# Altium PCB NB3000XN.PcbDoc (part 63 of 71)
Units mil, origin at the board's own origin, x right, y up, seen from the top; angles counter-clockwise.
Board outline 9527.56 x 6929.77 mil, 6 copper layers (Top Layer, GND+SHIELD, MidLayer1, MidLayer2, P2 - 3V3+5V0, Bottom Layer), stack 62.375 mil thick; 832 components, 1027 nets, 4655 pads, 4981 vias.
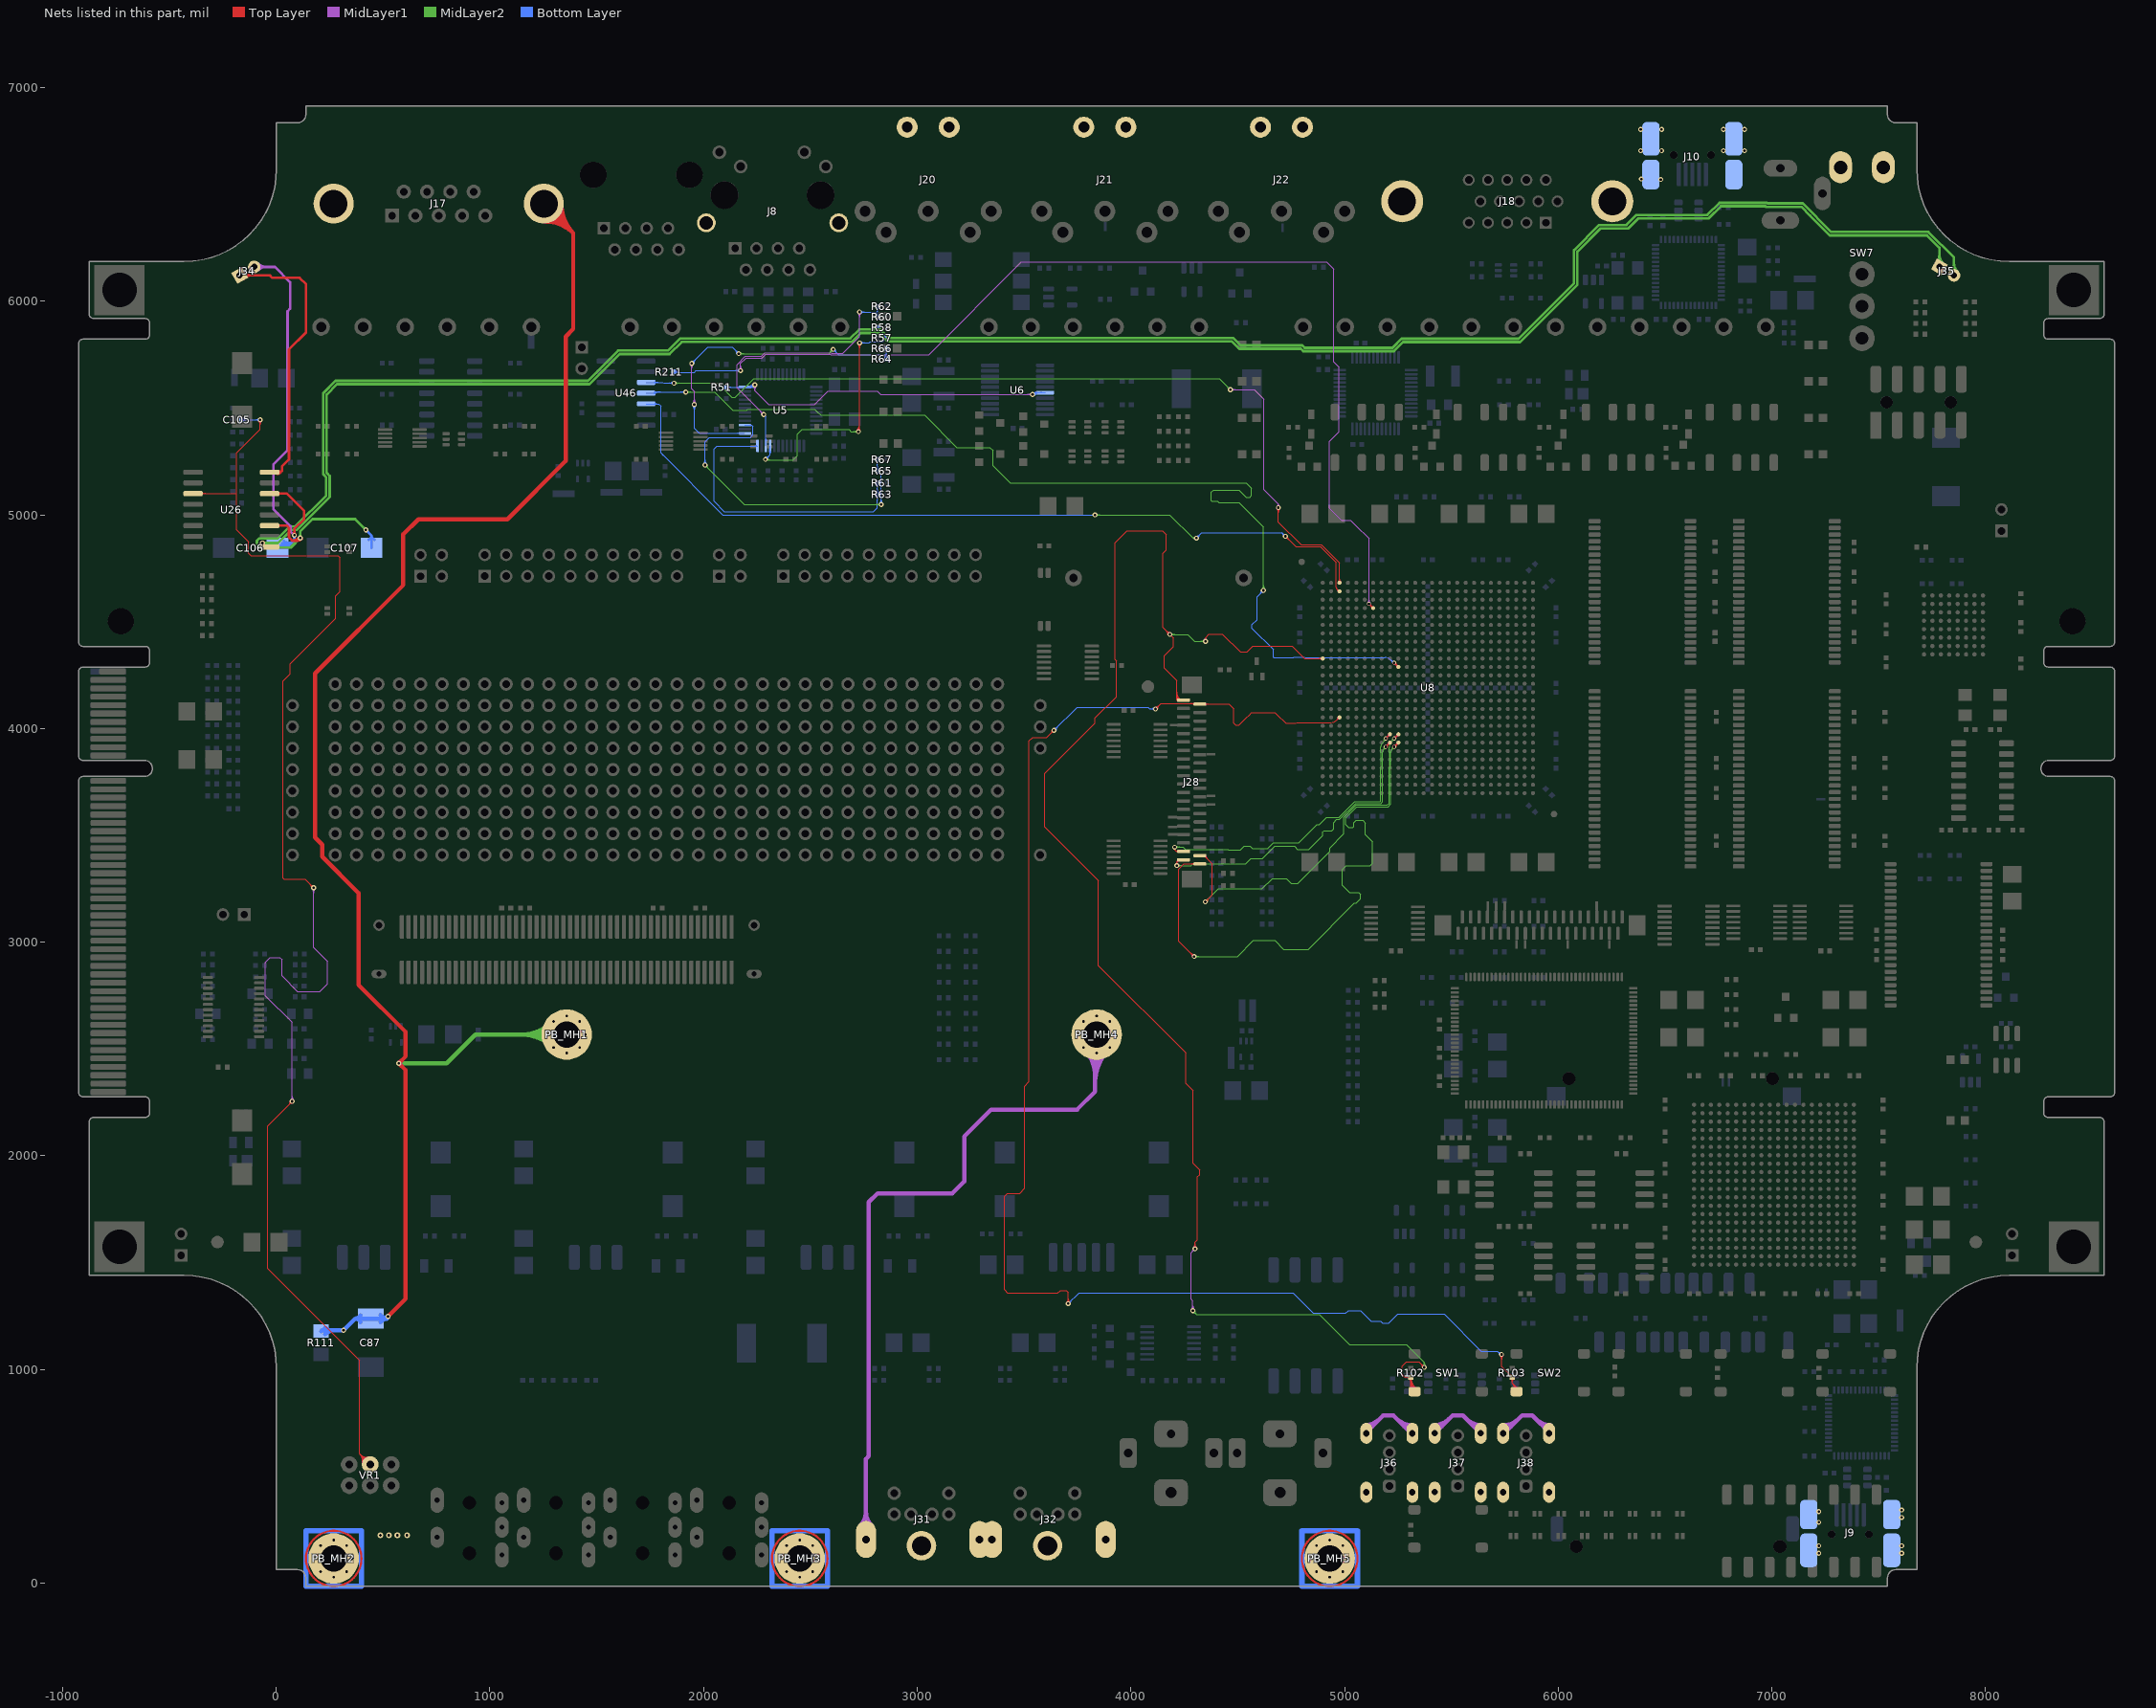
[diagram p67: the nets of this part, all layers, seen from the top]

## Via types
v1: diameter 23, hole 11.81, Top Layer to Bottom Layer, 3672 vias
v2: diameter 26, hole 11.81, Top Layer to Bottom Layer, 461 vias
v3: diameter 19, hole 11.81, Top Layer to Bottom Layer, tented both sides, 396 vias
v4: diameter 23.62, hole 11.81, Top Layer to Bottom Layer, 288 vias
v5: diameter 20, hole 11.81, Top Layer to Bottom Layer, 91 vias
v6: diameter 23, hole 11.81, Top Layer to Bottom Layer, tented both sides, 50 vias
v7: diameter 31, hole 11.81, Top Layer to Bottom Layer, 15 vias
v8: diameter 27.56, hole 11.81, Top Layer to Bottom Layer, tented both sides, 4 vias
v9: diameter 29, hole 11.81, Top Layer to Bottom Layer, 3 vias
v10: diameter 21, hole 11.81, Top Layer to Bottom Layer, 1 vias

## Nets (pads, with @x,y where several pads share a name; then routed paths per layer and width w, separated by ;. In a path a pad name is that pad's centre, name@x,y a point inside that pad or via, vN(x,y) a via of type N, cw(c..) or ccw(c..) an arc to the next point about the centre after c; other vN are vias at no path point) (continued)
RS485.RX_EN: U8.A3 U46.3 | length 4535.4
  Top Layer w4: v1@4683.47,5027.66 cw(c4667.26,5011.44) 4690.19,5011.44 cw(c4713.13,5011.44) v1@4696.91,5027.66 ; v1@4686.3,5030.49 cw(c4676.91,5021.1) 4690.19,5021.1 cw(c4703.47,5021.1) v1@4694.08,5030.49 ; v1(4690.19,5034.37) 4690.19,4966.71 4797.19,4859.71 4891.61,4859.71 4976.61,4774.7 4976.61,4724.74 4976.61,4720 4976.61,4710 U8.A3@4976.61,4682.13 ; U8.A3@4971.31,4687.43 ccw(c4958.51,4700.23) 4976.61,4700.23 ccw(c4994.72,4700.23) U8.A3@4981.92,4687.43 ; U8.A3@4971.42,4687.32 ccw(c4958.89,4699.85) 4976.61,4699.85 ccw(c4994.34,4699.85) U8.A3@4981.81,4687.32
  MidLayer1 w4: v1(4466.19,5586.04) 4578.96,5586.04 4623.52,5541.48 4623.52,5117.71 4690.19,5051.04 ; v1@4470.08,5582.15 cw(c4479.47,5572.76) 4479.47,5586.04 cw(c4479.47,5599.32) v1@4470.08,5589.93 ; v1@4472.91,5579.32 cw(c4489.13,5563.11) 4489.13,5586.04 cw(c4489.13,5608.98) v1@4472.91,5592.76 ; v1@4685.35,5042.55 ccw(c4680.32,5051.04) 4690.19,5051.04 ; v1(4690.19,5034.37) 4690.19,5051.04 ; v1@4695.03,5042.55 cw(c4700.06,5051.04) 4690.19,5051.04
  MidLayer2 w4: v1(1861.86,5616.71) 2065.19,5616.71 2131.86,5550.04 2148.52,5550.04 2231.86,5633.37 2236.29,5637.81 4414.42,5637.81 4418.86,5633.37 v1(4466.19,5586.04) ; v1@4456.69,5586.04 ccw(c4433.76,5586.04) 4449.97,5602.26 ccw(c4466.19,5618.48) v1@4466.19,5595.54 ; v1@4460.69,5586.04 ccw(c4447.41,5586.04) 4456.8,5595.43 ccw(c4466.19,5604.82) v1@4466.19,5591.54 ; 1875.14,5616.71 cw(c1875.14,5629.99) 1865.75,5620.6 ccw(c1875.14,5629.99) 1875.14,5616.71 ; 1875.14,5616.71 ccw(c1875.14,5603.43) 1865.75,5612.82 cw(c1875.14,5603.43) 1875.14,5616.71 ; 1884.79,5616.71 cw(c1884.79,5639.64) 1868.57,5623.43 ccw(c1884.79,5639.64) 1884.79,5616.71 ; 1884.79,5616.71 ccw(c1884.79,5593.77) 1868.57,5609.99 cw(c1884.79,5593.77) 1884.79,5616.71
  Bottom Layer w4: U46.3@1731.54,5620.08 1810,5620.08 1813.37,5616.71 v1(1861.86,5616.71) ; U46.3@1767.15,5615.97 cw(c1777.07,5606.05) 1777.07,5620.08 cw(c1777.07,5634.11) U46.3@1767.15,5624.19 ; U46.3@1769.98,5613.14 cw(c1786.72,5596.39) 1786.72,5620.08 cw(c1786.73,5643.76) U46.3@1769.98,5627.01 ; v1@1855.14,5609.99 ccw(c1838.92,5593.77) 1838.92,5616.71 ccw(c1838.92,5639.64) v1@1855.14,5623.43 ; v1@1857.97,5612.82 ccw(c1848.58,5603.43) 1848.58,5616.71 ccw(c1848.58,5629.99) v1@1857.97,5620.6
RS485.RXD: R211.1 U8.D7 | length 5431
  Top Layer w4: v3(5114.41,4583.7) U8.D7@5134.09,4564.02 ; U8.D7@5126.59,4564.02 ccw(c5108.49,4564.02) 5121.29,4576.82 ccw(c5134.09,4589.62) U8.D7@5134.09,4571.52 ; U8.D7@5126.75,4564.02 ccw(c5109.03,4564.02) 5121.56,4576.55 ccw(c5134.09,4589.08) U8.D7@5134.09,4571.36 ; 5127.21,4570.9 ccw(c5114.41,4558.09) 5114.41,4576.2 cw(c5114.41,4558.09) 5127.21,4570.9 ; 5127.21,4570.9 cw(c5140.02,4583.7) 5121.91,4583.7 ccw(c5140.02,4583.7) 5127.21,4570.9
  MidLayer1 w4: v1@2166.81,5681.76 ccw(c2150.59,5697.98) 2173.52,5697.98 ccw(c2196.46,5697.98) v1@2180.24,5681.76 ; v1@2169.64,5678.93 ccw(c2160.25,5688.32) 2173.52,5688.32 ccw(c2186.8,5688.32) v1@2177.41,5678.93 ; v1(2173.52,5675.04) 2173.52,5708.52 2199.21,5734.21 2274.21,5734.21 2291,5751 2594.84,5751 2596.29,5749.54 3054.54,5749.54 3488.37,6183.37 4916.63,6183.37 4950,6150 4950,5715.23 4973.52,5691.71 4973.52,5389.04 4929.52,5345.04 4929.52,5030.94 4985.43,4975.04 5028.45,4975.04 5051.23,4952.26 ; 5050,4953.49 5114.41,4889.08 5114.41,4720 5114.41,4710 5114.41,4661.38 v3(5114.41,4583.7) ; v3@5109.22,4588.89 ccw(c5096.68,4601.43) 5114.41,4601.43 ccw(c5132.14,4601.43) v3@5119.6,4588.89 ; 5114.41,4601.81 ccw(c5132.52,4601.81) 5119.71,4589 cw(c5132.52,4601.81) 5114.41,4601.81 ; 5114.41,4601.81 cw(c5096.3,4601.81) 5109.11,4589 ccw(c5096.3,4601.81) 5114.41,4601.81
  Bottom Layer w4: R211.1@1861.18,5670 1861.18,5666.71 1956.86,5666.71 1965.19,5675.04 v1(2173.52,5675.04) ; R211.1@1864.94,5673.27 ccw(c1880.78,5689.11) 1880.78,5666.71 ; R211.1@1867.77,5662.92 cw(c1876.92,5653.77) 1876.92,5666.71 ; R211.1@1867.77,5676.1 ccw(c1890.44,5698.77) 1890.44,5666.71 ; v1@2166.81,5668.32 ccw(c2150.59,5652.11) 2150.59,5675.04 ccw(c2150.59,5697.98) v1@2166.81,5681.76 ; v1@2169.64,5671.15 ccw(c2160.25,5661.76) 2160.25,5675.04 ccw(c2160.25,5688.32) v1@2169.64,5678.93
RS485.TX_EN: U8.L10 U46.4 | length 5352.4
  Top Layer w4: v3(5232.52,4308.11) U8.L10@5252.2,4288.43 ; U8.L10@5244.7,4288.43 ccw(c5226.6,4288.43) 5239.4,4301.23 ccw(c5252.2,4314.03) U8.L10@5252.2,4295.93 ; U8.L10@5244.86,4288.43 ccw(c5227.14,4288.43) 5239.67,4300.96 ccw(c5252.2,4313.49) U8.L10@5252.2,4295.77 ; 5245.32,4295.31 cw(c5258.13,4308.11) 5240.02,4308.11 ccw(c5258.13,4308.11) 5245.32,4295.31 ; 5245.32,4295.31 ccw(c5232.52,4282.5) 5232.52,4300.61 cw(c5232.52,4282.5) 5245.32,4295.31
  MidLayer2 w4: v1(1916.86,5575.04) 2051.86,5575.04 2127.99,5498.91 2137.02,5489.88 2201.5,5489.88 2207.17,5495.54 2519.69,5495.54 2533.5,5481.74 2548.52,5466.71 3034.84,5466.71 3185.41,5316.14 3340.18,5316.14 3355,5301.31 3355,5230 3434.96,5150.04 4540.19,5150.04 4565.19,5125.04 4565.19,5091.71 4556.86,5083.37 4540.19,5083.37 4506.86,5116.71 4386.71,5116.71 4377.28,5107.28 4377.28,5067.72 4379.5,5065.5 4405.56,5065.5 4412.69,5058.37 4506.86,5058.37 4590.12,4975.12 ; v1@1920.75,5571.15 cw(c1930.14,5561.76) 1930.14,5575.04 cw(c1930.14,5588.32) v1@1920.75,5578.93 ; v1@1923.57,5568.32 cw(c1939.79,5552.11) 1939.79,5575.04 cw(c1939.79,5597.98) v1@1923.57,5581.76 ; 4590,4975 4620.52,4944.48 v1(4620.52,4647.04) ; v1@4613.81,4653.76 ccw(c4597.59,4669.98) 4620.52,4669.98 ccw(c4643.46,4669.98) v1@4627.24,4653.76 ; v1@4616.64,4650.93 ccw(c4607.25,4660.32) 4620.52,4660.32 ccw(c4633.8,4660.32) v1@4624.41,4650.93
  Bottom Layer w4: U46.4@1731.54,5570.08 1763.04,5570.08 1765.19,5570.08 1765.19,5570.37 1769.86,5575.04 v1(1916.86,5575.04) ; U46.4@1764.32,5568.8 cw(c1779.39,5553.72) 1779.39,5575.04 ; U46.4@1767.15,5565.97 cw(c1789.05,5544.07) 1789.05,5575.04 ; U46.4@1769.98,5563.14 cw(c1798.71,5534.41) 1798.71,5575.04 ; U46.4@1769.98,5577.01 ccw(c1774.74,5581.78) U46.4@1774.74,5575.04 ; v1@1910.14,5568.32 ccw(c1893.92,5552.11) 1893.92,5575.04 ccw(c1893.92,5597.98) v1@1910.14,5581.76 ; v1@1912.97,5571.15 ccw(c1903.58,5561.76) 1903.58,5575.04 ccw(c1903.58,5588.32) v1@1912.97,5578.93 ; v1@4611.02,4647.04 cw(c4588.09,4647.04) 4604.31,4630.82 cw(c4620.52,4614.61) v1@4620.52,4637.54 ; v1@4615.02,4647.04 cw(c4601.75,4647.04) 4611.13,4637.65 cw(c4620.52,4628.26) v1@4620.52,4641.54 ; v1(4620.52,4647.04) 4590.19,4616.71 4590.19,4508.63 4567.5,4485.94 4567.5,4469.69 4667.19,4370 4667.19,4333.37 4668.52,4332.04 4761.88,4332.04 4764.84,4335 4813.75,4335 4816.78,4331.97 4860,4331.97 4870,4331.97 5076.1,4331.97 5095.52,4331.97 5169.64,4331.97 5189.14,4331.97 cw(c5189.14,4290.24) 5218.65,4319.75 ; v3@5225.05,4307.46 ccw(c5207.01,4305.88) 5218.65,4319.75 ; v3@5231.87,4315.58 cw(c5230.29,4333.62) 5218.65,4319.75
RS485.TXD: U8.B3 U46.5 | length 4162.6
  Top Layer w4: v1@4723.52,4890.54 cw(c4723.52,4867.61) 4739.74,4883.82 cw(c4755.96,4900.04) v1@4733.02,4900.04 ; v1@4723.52,4894.54 cw(c4723.52,4881.26) 4732.91,4890.65 cw(c4742.3,4900.04) v1@4729.02,4900.04 ; v1(4723.52,4900.04) 4771.86,4851.71 4888.17,4851.71 4889.67,4850.21 4889.79,4850.21 4961.11,4778.89 4961.11,4720 ; 4961.11,4724.74 4961.11,4720 ; 4961.11,4662.47 ccw(c4971.26,4662.47) 4964.08,4655.29 ; 4961.11,4662.47 ccw(c4971.26,4662.47) 4964.08,4655.29 ; 4961.11,4662.47 4961.11,4710 4961.11,4720 ; 4964.08,4655.29 ccw(c4976.61,4667.83) 4976.61,4650.1 cw(c4976.61,4667.83) 4964.08,4655.29 ; 4964.08,4655.29 cw(c4951.55,4642.76) 4969.27,4642.76 ccw(c4951.55,4642.76) 4964.08,4655.29
  MidLayer2 w4: v1(3831.86,5000.04) 4181.86,5000.04 4290.19,4891.71 ; v1@3835.75,4996.15 cw(c3845.14,4986.76) 3845.14,5000.04 cw(c3845.14,5013.32) v1@3835.75,5003.93 ; v1@3838.57,4993.32 cw(c3854.79,4977.11) 3854.79,5000.04 cw(c3854.79,5022.98) v1@3838.57,5006.76 ; v1@4298.68,4886.87 ccw(c4290.19,4881.84) 4290.19,4891.71 ; v1@4298.68,4896.55 cw(c4290.19,4901.58) 4290.19,4891.71 ; v1(4306.86,4891.71) 4290.19,4891.71
  Bottom Layer w4: U46.5@1731.54,5520.08 1780,5520.08 ; U46.5@1771.54,5515.19 cw(c1780,5510.32) 1780,5520.08 ; U46.5@1771.54,5524.97 ccw(c1780,5529.83) 1780,5520.08 ; 1810.61,5279.62 1800,5290.23 ; v1(3831.86,5000.04) 2090.19,5000.04 1800,5290.23 ; v1(4306.86,4891.71) 4332.19,4917.04 4706.52,4917.04 v1(4723.52,4900.04) ; v1@4306.86,4897.21 ccw(c4306.86,4910.49) 4316.25,4901.1 ccw(c4325.64,4891.71) v1@4312.36,4891.71 ; v1@4306.86,4901.21 ccw(c4306.86,4924.14) 4323.07,4907.93 ccw(c4339.29,4891.71) v1@4316.36,4891.71 ; v1@4714.02,4900.04 ccw(c4691.09,4900.04) 4707.31,4916.26 ccw(c4723.52,4932.48) v1@4723.52,4909.54 ; v1@4718.02,4900.04 ccw(c4704.75,4900.04) 4714.14,4909.43 ccw(c4723.52,4918.82) v1@4723.52,4905.54 ; 1780,5520.08 1789.92,5520.08 1800,5510 1800,5290.23
RXER_U: R51.1 U5.24 U6.6 | length 2078.5
  MidLayer1 w4: v1@2233.47,5601.66 cw(c2217.26,5585.44) 2240.19,5585.44 cw(c2263.13,5585.44) v1@2246.91,5601.66 ; v1@2236.3,5604.49 cw(c2226.91,5595.1) 2240.19,5595.1 cw(c2253.47,5595.1) v1@2244.08,5604.49 ; v1(2240.19,5608.37) 2240.19,5581.37 2304.86,5516.71 2456.86,5516.71 2520.39,5516.71 2582.69,5579 2813.82,5579 2828.78,5564.04 v1(3540.19,5564.04) ; v1@3533.47,5557.32 ccw(c3517.26,5541.11) 3517.26,5564.04 ccw(c3517.26,5586.98) v1@3533.47,5570.76 ; v1@3536.3,5560.15 ccw(c3526.91,5550.76) 3526.91,5564.04 ccw(c3526.91,5577.32) v1@3536.3,5567.93
  Bottom Layer w4: R51.1@2106.18,5598.33 U5.24@2193.48,5598.33 ; R51.1@2109.94,5594.57 cw(c2119.02,5585.49) 2119.02,5598.33 cw(c2119.02,5611.18) R51.1@2109.94,5602.09 ; R51.1@2112.77,5591.74 cw(c2128.68,5575.84) 2128.68,5598.33 cw(c2128.68,5620.83) R51.1@2112.77,5604.92 ; 2160.2,5598.33 cw(c2160.2,5588.45) U5.24@2167.19,5595.44 ; 2160.52,5598.33 ccw(c2160.52,5607.77) U5.24@2167.19,5601.1 ; U5.24@2203.06,5598.27 ccw(c2203.06,5644.73) v1@2236.26,5612.22 ; U5.24@2212.58,5598.27 ccw(c2212.58,5635.42) v1@2239.12,5609.42 ; U5.24@2219.9,5595.44 cw(c2226.73,5588.61) 2226.73,5598.27 cw(c2226.73,5607.92) U5.24@2219.9,5601.1 ; U5.24@2222.09,5598.27 ccw(c2222.09,5626.1) v1@2241.98,5606.63 ; 2231.61,5598.27 ccw(c2231.61,5616.78) v1@2244.83,5603.83 ; v1@2233.4,5615.02 cw(c2193.55,5654.05) U5.24@2193.54,5598.27 2238.42,5598.27 2240.19,5600.04 v1(2240.19,5608.37) ; v1@3538.42,5565.81 cw(c3553.86,5550.37) 3553.86,5572.2 ; v1(3540.19,5564.04) 3548.35,5572.2 U6.6@3598.94,5572.2 ; v1@3541.25,5562.98 cw(c3563.52,5540.71) U6.6@3563.52,5572.2 ; v1@3544.08,5560.15 cw(c3573.18,5531.05) U6.6@3573.18,5572.2 ; v1@3546.91,5557.32 cw(c3582.83,5521.4) U6.6@3582.83,5572.2 ; U6.6@3560.62,5567.36 ccw(c3548.92,5555.65) 3548.92,5572.2 ccw(c3548.92,5588.76) U6.6@3560.62,5577.05
S_LED0: R57.1 R58.1 U5.9 | length 1810.4
  Top Layer w4: v4@2718.06,5396.94 ccw(c2689.24,5425.76) 2730,5425.76 ; v4@2720.89,5394.11 ccw(c2698.9,5416.1) 2730,5416.1 ; v4@2723.06,5798.06 cw(c2706.31,5781.31) 2730,5781.31 cw(c2753.69,5781.31) v4@2736.94,5798.06 ; v4@2723.72,5391.28 ccw(c2708.56,5406.44) 2730,5406.44 ; v4(2725,5390) 2730,5395 v4(2730,5805) ; v4@2725.89,5800.89 cw(c2715.97,5790.97) 2730,5790.97 cw(c2744.03,5790.97) v4@2734.11,5800.89 ; 2730,5401.61 ccw(c2736.61,5401.61) v4@2731.94,5396.94
  MidLayer2 w4: v4(2290,5260) 2292.46,5257.54 2420,5257.54 2439.7,5277.24 2439.7,5377.53 2462.7,5400.54 2680,5400.54 2690.54,5390 v4(2725,5390) ; v4@2294.11,5264.11 ccw(c2309.97,5279.97) 2309.97,5257.54 ; v4@2296.94,5253.06 cw(c2307.75,5242.25) 2307.75,5257.54 ; v4@2296.94,5266.94 ccw(c2319.62,5289.62) 2319.62,5257.54 ; v4@2718.06,5383.06 ccw(c2701.31,5366.31) 2701.31,5390 ccw(c2701.31,5413.69) v4@2718.06,5396.94 ; v4@2720.89,5385.89 ccw(c2710.97,5375.97) 2710.97,5390 ccw(c2710.97,5404.03) v4@2720.89,5394.11
  Bottom Layer w4: v4(2290,5260) 2311.65,5281.65 U5.9@2311.65,5322.68 ; v4@2290,5265.81 ccw(c2290,5279.84) 2299.92,5269.92 ccw(c2309.84,5260) v4@2295.81,5260 ; v4@2290,5269.81 ccw(c2290,5293.5) 2306.75,5276.75 ccw(c2323.5,5260) v4@2299.81,5260 ; U5.9@2308.82,5296.32 cw(c2302,5289.49) 2311.65,5289.49 cw(c2321.31,5289.49) U5.9@2314.48,5296.32 ; v4(2730,5805) 2774.96,5805 2780,5810.04 2838.22,5810.04 R57.1@2856.18,5828 ; v4@2734.11,5800.89 cw(c2744.03,5790.97) 2744.03,5805 cw(c2744.03,5819.03) v4@2734.11,5809.11 ; v4@2736.94,5798.06 cw(c2753.69,5781.31) 2753.69,5805 cw(c2753.69,5828.69) v4@2736.94,5811.94 ; R58.1@2813.82,5867.19 cw(c2813.82,5843.5) 2830.57,5860.25 ; R58.1@2813.82,5871.19 cw(c2813.82,5857.16) R58.1@2823.74,5867.08 ; R58.1@2813.82,5877 R57.1@2856.18,5834.64 ; R58.1@2819.14,5876.51 ccw(c2830.79,5876.51) R58.1@2822.55,5868.27 ; R58.1@2823.14,5876.51 ccw(c2844.45,5876.51) 2829.38,5861.44 ; 2835.93,5854.89 cw(c2809.53,5828.49) R57.1@2846.86,5828.49 ; 2839.43,5811.25 cw(c2856.18,5794.5) R57.1@2856.18,5818.19 ; 2840.62,5812.44 ccw(c2825.55,5827.51) R57.1@2846.86,5827.51 ; 2842.76,5848.06 cw(c2823.18,5828.49) R57.1@2850.86,5828.49 ; R57.1@2846.26,5818.08 cw(c2856.18,5808.16) R57.1@2856.18,5822.19 ; R57.1@2847.45,5819.27 ccw(c2839.21,5827.51) R57.1@2850.86,5827.51 ; 2849.58,5841.23 cw(c2836.84,5828.49) R57.1@2854.86,5828.49 ; 2850.76,5840.05 ccw(c2856.18,5845.47) R57.1@2856.18,5837.81
S_LED1: R60.2 R62.1 U5.10 | length 1575.8
  MidLayer1 w4: v1@2272.36,5470.04 ccw(c2249.42,5470.04) 2265.64,5486.26 ccw(c2281.86,5502.48) v1@2281.86,5479.54 ; v1@2276.36,5470.04 ccw(c2263.08,5470.04) 2272.47,5479.43 ccw(c2281.86,5488.82) v1@2281.86,5475.54 ; v1(2281.86,5470.04) 2156.02,5595.87 2156.02,5702.34 2195.89,5742.21 2267.21,5742.21 2270.89,5742.21 2287.69,5759 2598.15,5759 2599.61,5757.54 2652.54,5757.54 2730,5835 v1(2730,5950) ; v1@2723.28,5943.28 cw(c2707.06,5927.06) 2730,5927.06 cw(c2752.93,5927.06) v1@2736.72,5943.28 ; v1@2726.11,5946.11 cw(c2716.72,5936.72) 2730,5936.72 cw(c2743.28,5936.72) v1@2733.89,5946.11
  Bottom Layer w4: v1(2281.86,5470.04) 2291.97,5459.93 U5.10@2291.97,5322.68 ; U5.10@2289.14,5349.03 ccw(c2282.31,5355.86) 2291.97,5355.86 ccw(c2301.63,5355.86) U5.10@2294.8,5349.03 ; v1(2730,5950) 2805.49,5950.04 ; v1@2733.89,5946.11 cw(c2743.29,5936.73) 2743.28,5950.01 cw(c2743.27,5963.29) v1@2733.89,5953.89 ; v1@2736.72,5943.29 cw(c2752.95,5927.08) 2752.94,5950.01 cw(c2752.92,5972.95) v1@2736.71,5956.72 ; R62.1@2807.23,5967.92 cw(c2791.32,5952.01) 2813.82,5952.01 cw(c2836.32,5952.01) R62.1@2820.41,5967.92 ; R60.2@2809.58,5934.79 ccw(c2806.06,5941.71) 2813.82,5941.71 ; R62.1@2810.06,5970.75 cw(c2800.98,5961.67) 2813.82,5961.67 cw(c2826.66,5961.67) R62.1@2817.58,5970.75 ; 2813.78,5950.04 2805.49,5950.04 ; R60.2@2813.82,5926 2813.82,5941.71 ; 2813.82,5950 R62.1@2813.82,5975 ; R60.2@2818.05,5934.79 cw(c2821.58,5941.71) 2813.82,5941.71 ; 2805.49,5950.04 2813.82,5941.71
S_LED2: R61.1 R63.1 U5.12 | length 1544.7
  Bottom Layer w4: 2242.62,5322.81 cw(c2242.62,5312.7) U5.12@2249.77,5319.85 ; 2243.26,5322.81 ccw(c2243.26,5332.01) U5.12@2249.77,5325.51 ; U5.12@2252.6,5322.68 2252.46,5322.81 2062.96,5322.81 2048.52,5308.37 2048.52,5064.34 2096.82,5016.04 2796.04,5016.04 2813.82,5033.82 R61.1@2813.82,5150 ; R63.1@2807.23,5087.92 cw(c2791.32,5072.01) 2813.82,5072.01 cw(c2836.32,5072.01) R63.1@2820.41,5087.92 ; R63.1@2807.23,5102.08 ccw(c2791.32,5117.99) 2813.82,5117.99 ccw(c2836.32,5117.99) R63.1@2820.41,5102.08 ; R61.1@2807.23,5142.92 cw(c2791.32,5127.01) 2813.82,5127.01 cw(c2836.32,5127.01) R61.1@2820.41,5142.92 ; R63.1@2810.06,5090.75 cw(c2800.98,5081.67) 2813.82,5081.67 cw(c2826.66,5081.67) R63.1@2817.58,5090.75 ; R63.1@2810.06,5099.25 ccw(c2800.98,5108.33) 2813.82,5108.33 ccw(c2826.66,5108.33) R63.1@2817.58,5099.25 ; R61.1@2810.06,5145.75 cw(c2800.98,5136.67) 2813.82,5136.67 cw(c2826.66,5136.67) R61.1@2817.58,5145.75
S_LED3: R64.2 R66.1 U5.13 | length 2165.1
  MidLayer1 w4: v4@1938.06,5703.06 cw(c1921.31,5686.31) 1945,5686.31 cw(c1968.69,5686.31) v4@1951.94,5703.06 ; v4@1940.89,5705.89 cw(c1930.97,5695.97) 1945,5695.97 cw(c1959.03,5695.97) v4@1949.11,5705.89 ; v4(1945,5710) 1945,5590 1956.86,5578.14 v1(1956.86,5516.71) ; v1@1950.14,5523.43 ccw(c1933.92,5539.64) 1956.86,5539.64 ccw(c1979.79,5539.64) v1@1963.57,5523.43 ; v1@1952.97,5520.6 ccw(c1943.58,5529.99) 1956.86,5529.99 ccw(c1970.14,5529.99) v1@1960.75,5520.6
  MidLayer2 w4: v4(2165,5755) 2586.82,5755 v1(2606.86,5775.04) ; v4@2169.11,5750.89 cw(c2179.03,5740.97) 2179.03,5755 cw(c2179.03,5769.03) v4@2169.11,5759.11 ; v4@2171.94,5748.06 cw(c2188.69,5731.31) 2188.69,5755 cw(c2188.69,5778.69) v4@2171.94,5761.94 ; v1@2597.36,5775.04 cw(c2574.42,5775.04) 2590.64,5758.82 cw(c2606.86,5742.61) v1@2606.86,5765.54 ; v1@2601.36,5775.04 cw(c2588.08,5775.04) 2597.47,5765.65 cw(c2606.86,5756.26) v1@2606.86,5769.54
  Bottom Layer w4: v4(1945,5710) 2020,5785 2135,5785 v4(2165,5755) ; v4@1945,5715.81 ccw(c1945,5729.84) 1954.92,5719.92 ccw(c1964.84,5710) v4@1950.81,5710 ; v4@1945,5719.81 ccw(c1945,5743.5) 1961.75,5726.75 ccw(c1978.5,5710) v4@1954.81,5710 ; v1@1950.14,5509.99 cw(c1933.92,5493.77) 1956.86,5493.77 cw(c1979.79,5493.77) v1@1963.57,5509.99 ; v1@1952.97,5512.82 cw(c1943.58,5503.43) 1956.86,5503.43 cw(c1970.14,5503.43) v1@1960.75,5512.82 ; v1(1956.86,5516.71) 1956.86,5405 1980.13,5381.73 U5.13@2193.54,5381.73 ; v4@2155.19,5755 ccw(c2131.5,5755) 2148.25,5771.75 ccw(c2165,5788.5) v4@2165,5764.81 ; v4@2159.19,5755 ccw(c2145.16,5755) 2155.08,5764.92 ccw(c2165,5774.84) v4@2165,5760.81 ; U5.13@2167.19,5378.9 ccw(c2160.36,5372.08) 2160.36,5381.73 ccw(c2160.36,5391.39) U5.13@2167.19,5384.56 ; v1@2606.86,5765.54 cw(c2606.86,5742.61) 2623.07,5758.82 cw(c2639.29,5775.04) v1@2616.36,5775.04 ; v1@2606.86,5769.54 cw(c2606.86,5756.26) 2616.25,5765.65 cw(c2625.64,5775.04) v1@2612.36,5775.04 ; v1(2606.86,5775.04) 2631.86,5750.04 2854.51,5750.04 2856.18,5751.71 ; R66.1@2849.59,5771.92 cw(c2833.68,5756.01) 2856.18,5756.01 cw(c2878.68,5756.01) R66.1@2862.77,5771.92 ; R64.2@2849.88,5737.35 ccw(c2836.69,5751.71) 2856.18,5751.71 ; R66.1@2852.42,5774.75 cw(c2843.34,5765.67) 2856.18,5765.67 cw(c2869.02,5765.67) R66.1@2859.94,5774.75 ; R64.2@2852.58,5734.41 ccw(c2845.06,5742.6) 2856.18,5742.6 ccw(c2867.3,5742.6) R64.2@2859.78,5734.41 ; R64.2@2856.18,5730 2856.18,5751.71 ; R66.1@2856.18,5779 2856.18,5751.71 ; R64.2@2862.49,5737.35 cw(c2875.67,5751.71) 2856.18,5751.71
S_LED4: R65.1 R67.1 U5.15 | length 1954.1
  MidLayer2 w4: v1@2006.86,5223.87 cw(c2006.86,5200.94) 2023.07,5217.16 cw(c2039.29,5233.37) v1@2016.36,5233.37 ; v1@2006.86,5227.87 cw(c2006.86,5214.6) 2016.25,5223.99 cw(c2025.64,5233.37) v1@2012.36,5233.37 ; v1(2006.86,5233.37) 2191.52,5048.71 v1(2831.86,5048.71) ; v1@2825.14,5041.99 ccw(c2808.92,5025.77) 2808.92,5048.71 ccw(c2808.92,5071.64) v1@2825.14,5055.43 ; v1@2827.97,5044.82 ccw(c2818.58,5035.43) 2818.58,5048.71 ccw(c2818.58,5061.99) v1@2827.97,5052.6
  Bottom Layer w4: v1@2000.14,5240.09 ccw(c1983.92,5256.31) 2006.86,5256.31 ccw(c2029.79,5256.31) v1@2013.57,5240.09 ; v1@2002.97,5237.26 ccw(c1993.58,5246.65) 2006.86,5246.65 ccw(c2020.14,5246.65) v1@2010.75,5237.26 ; v1(2006.86,5233.37) 2006.86,5342.05 2027.62,5362.81 2219.63,5362.81 2231.86,5375.04 2231.86,5413.1 2223.86,5421.1 U5.15@2193.54,5421.1 ; U5.15@2217.07,5421.1 cw(c2217.25,5405.15) 2228.53,5416.43 ; R65.1@2807.23,5212.08 ccw(c2791.32,5227.99) 2813.82,5227.99 ccw(c2836.32,5227.99) R65.1@2820.41,5212.08 ; R67.1@2807.23,5252.92 cw(c2791.32,5237.01) 2813.82,5237.01 cw(c2836.32,5237.01) R67.1@2820.41,5252.92 ; R65.1@2810.06,5209.25 ccw(c2800.98,5218.33) 2813.82,5218.33 ccw(c2826.66,5218.33) R65.1@2817.58,5209.25 ; R67.1@2810.06,5255.75 cw(c2800.98,5246.67) 2813.82,5246.67 cw(c2826.66,5246.67) R67.1@2817.58,5255.75 ; R65.1@2813.82,5195.19 cw(c2813.82,5171.5) 2830.57,5188.25 ; R65.1@2813.82,5199.19 cw(c2813.82,5185.16) R65.1@2823.74,5195.08 ; R67.1@2813.82,5260 R65.1@2813.82,5205 2831.86,5186.96 v1(2831.86,5048.71) ; R65.1@2819.14,5204.51 ccw(c2830.79,5204.51) R65.1@2822.55,5196.27 ; R65.1@2823.14,5204.51 ccw(c2844.45,5204.51) 2829.38,5189.44 ; v1@2825.14,5055.43 ccw(c2808.92,5071.64) 2831.86,5071.64 ccw(c2854.79,5071.64) v1@2838.57,5055.43 ; v1@2827.97,5052.6 ccw(c2818.58,5061.99) 2831.86,5061.99 ccw(c2845.14,5061.99) v1@2835.75,5052.6
SHIELD: C87.1 J8.MH1 J8.MH2 J9.6 J9.7 J9.8 J9.9 J10.6 J10.7 J10.8 J10.9 J17.10 J17.11 J18.16 J18.17 J20.MH1 J20.MH2 J21.MH1 J21.MH2 J22.MH1 J22.MH2 J31.MH1 J31.MH2 J31.MH3 J32.MH1 J32.MH2 J32.MH3 J36.MH1 J36.MH2 J36.MH3 J36.MH4 J37.MH1 J37.MH2 J37.MH3 J37.MH4 J38.MH1 J38.MH2 J38.MH3 J38.MH4 PB_MH1.STAND PB_MH2.STAND PB_MH3.STAND PB_MH4.STAND PB_MH5.STAND R111.1 SW7.S1 SW7.S2 | length 14956.3
  Top Layer w20: v1(523.52,1248.71) 606,1331.18 606,2400.9 v1(573.52,2433.37) 606,2465.85 606,2580.06 385,2801.06 385,3230 215,3400 215,3456.86 181.86,3490 181.86,4258.57 595,4671.72 595,4910 665,4980 1082.19,4980 1355.5,5253.31 1355.5,5389.5 1355,5390 1355,5835 1390,5870 1390,6319.61 J17.10@1252.51,6457.09 ; J17.10@1253.72,6413.41 cw(c1256.38,6317.4) 1324.29,6385.31 cw(c1392.21,6453.23) J17.10@1296.2,6455.89 ; J17.10@1254.27,6393.42 cw(c1258.14,6253.47) 1357.14,6352.46 cw(c1456.14,6451.46) J17.10@1316.19,6455.33 ; J17.10@1254.83,6373.43 cw(c1259.91,6189.53) 1389.99,6319.61 cw(c1520.07,6449.69) J17.10@1336.18,6454.78
  MidLayer1 w20: J31.MH3@2734.02,270.27 ccw(c2670.44,333.85) 2760.35,333.85 ccw(c2850.27,333.85) J31.MH3@2786.69,270.27 ; J31.MH3@2760.35,204.57 2760.35,581.83 2773.52,595 2773.52,1783.52 2815,1825 3165.15,1825 3220.07,1879.93 3220.07,2090.07 3346.71,2216.71 3748.52,2216.71 3831.86,2300.04 3831.86,2481.3 3831.86,2567.91 3831.86,2575.04 3839.98,2575.04 PB_MH4.STAND@3839.98,2567.91 ; PB_MH4.STAND@3777.46,2505.38 cw(c3646.12,2374.05) 3831.86,2374.05 ; PB_MH4.STAND@3791.6,2519.53 cw(c3694.41,2422.34) 3831.86,2422.34 ; 3831.86,2334.82 cw(c4073.08,2334.82) PB_MH4.STAND@3902.51,2505.38 ; 3831.86,2383.1 cw(c4024.79,2383.1) PB_MH4.STAND@3888.37,2519.53 ; 3831.86,2431.38 cw(c3976.51,2431.38) PB_MH4.STAND@3874.22,2533.67 ; 3831.86,2457.31 cw(c3863.97,2457.31) PB_MH4.STAND@3841.26,2480.02 ; PB_MH4.STAND@3831.86,2505.29 ccw(c3863.97,2505.29) PB_MH4.STAND@3841.26,2482.58 ; J36.MH4@5097.22,701.18 5181.04,785 5228.75,785 J36.MH3@5312.57,701.18 ; J36.MH4@5097.22,720.39 ccw(c5097.22,766.78) 5130.02,733.98 ; J36.MH4@5097.22,740.39 ccw(c5097.22,835.06) 5164.16,768.12 ; 5245.63,768.12 ccw(c5312.57,835.06) J36.MH3@5312.57,740.39 ; 5279.77,733.98 ccw(c5312.57,766.78) J36.MH3@5312.57,720.39 ; J37.MH4@5422.22,701.57 5506.04,785.39 5553.75,785.39 J37.MH3@5637.57,701.57 ; J37.MH4@5422.22,720.79 ccw(c5422.22,767.17) 5455.02,734.37 ; J37.MH4@5422.22,740.79 ccw(c5422.22,835.46) 5489.16,768.51 ; 5570.63,768.51 ccw(c5637.57,835.46) J37.MH3@5637.57,740.79 ; 5604.77,734.37 ccw(c5637.57,767.17) J37.MH3@5637.57,720.79 ; J38.MH4@5747.22,701.18 5831.04,785 5878.75,785 J38.MH3@5962.57,701.18 ; J38.MH4@5747.22,720.39 ccw(c5747.22,766.78) 5780.02,733.98 ; J38.MH4@5747.22,740.39 ccw(c5747.22,835.06) 5814.16,768.12 ; 5895.63,768.12 ccw(c5962.57,835.06) J38.MH3@5962.57,740.39 ; 5929.77,733.98 ccw(c5962.57,766.78) J38.MH3@5962.57,720.39
  MidLayer2 w20: v1(573.52,2433.37) 797.32,2433.37 931.86,2567.91 v4(1273.05,2567.91) PB_MH1.STAND@1359.67,2567.91 ; PB_MH1.STAND@1297.14,2505.38 ccw(c1146.19,2354.43) 1146.19,2567.91 ccw(c1146.19,2781.39) PB_MH1.STAND@1297.14,2630.44 ; PB_MH1.STAND@1311.28,2519.53 ccw(c1194.48,2402.72) 1194.48,2567.91 ccw(c1194.47,2733.1) PB_MH1.STAND@1311.28,2616.29 ; PB_MH1.STAND@1325.43,2533.67 ccw(c1242.76,2451) 1242.76,2567.91 ccw(c1242.76,2684.82) PB_MH1.STAND@1325.43,2602.15
  Bottom Layer w20: R111.1@210,1180.12 213.26,1183.37 v1(315.19,1183.37) 370,1238.19 ; R111.1@229.14,1164.92 cw(c273.7,1120.36) 273.7,1183.37 ; R111.1@229.14,1195.32 ccw(c257.97,1224.15) 257.97,1183.37 ; C87.1@394.75,1222.58 ccw(c370.01,1210.77) 370.01,1238.19 ; C87.1@394.75,1253.8 cw(c370.01,1265.61) 370.01,1238.19 ; C87.1@488.79,1220.75 cw(c518.26,1204.58) 518.26,1238.19 ; C87.1@488.79,1255.63 ccw(c518.26,1271.8) 518.26,1238.19 ; C87.1@494.51,1238.19 ccw(c494.51,1277.72) v1@522.46,1249.77 ; v1(523.52,1248.71) 523.52,1243.45 518.26,1238.19 ; J18.17@5269.76,6468 5273.52,6468 J18.17@5316.48,6425.04 ; J18.16@6210.66,6425.04 J18.16@6253.61,6468 ; 370,1238.19 439.24,1238.19 518.26,1238.19
  other v1: 7220,140 7607.8,140 7220,175 7607.8,175 7220,285 7607.8,307.32 7220,335 7607.8,342.32 6480,6570 6389.1,6571.98 6385.9,6704.66 6484.1,6704.66 6773.7,6704.66 6871.89,6704.66 6385.9,6804.66 6484.1,6804.66 6773.7,6804.66 6871.89,6804.66
  other v4: 269.12,28.54 2450.22,28.54 4930.54,28.54 207.87,53.91 330.36,53.91 2388.97,53.91 2511.47,53.91 4869.29,53.91 4991.78,53.91 182.5,115.16 355.73,115.16 2363.61,115.16 2536.83,115.16 4843.92,115.16 5017.15,115.16 207.87,176.4 330.36,176.4 2388.97,176.4 2511.47,176.4 4869.29,176.4 4991.78,176.4 269.12,201.77 2450.22,201.77 4930.54,201.77 1359.67,2481.3 3839.98,2481.3 1298.42,2506.67 1420.91,2506.67 3778.74,2506.67 3901.23,2506.67 1446.28,2567.91 3753.37,2567.91 3926.6,2567.91 1298.42,2629.16 1420.91,2629.16 3778.74,2629.16 3901.23,2629.16 1359.67,2654.53 3839.98,2654.53
  other v8: 487.34,224.08 527.34,224.08 567.34,224.08 612.34,224.08
SPAREIO.1: J28.37 U8.W9 | length 1714.4
  Top Layer w4: v1(4204.86,3444.71) 4204.86,3433.2 4212.86,3425.2 ; J28.37@4219.76,3421.71 ccw(c4212.86,3416.62) 4212.86,3425.2 ; J28.37@4219.76,3428.68 cw(c4212.86,3433.77) 4212.86,3425.2 ; J28.37@4246.61,3425.2 4212.86,3425.2 ; v3(5193.15,3953.78) U8.W9@5212.83,3973.46 ; U8.W9@5205.33,3973.46 cw(c5187.23,3973.46) 5200.03,3960.66 cw(c5212.83,3947.86) U8.W9@5212.83,3965.96 ; U8.W9@5205.49,3973.46 cw(c5187.77,3973.46) 5200.3,3960.93 cw(c5212.83,3948.4) U8.W9@5212.83,3966.12 ; 5205.95,3966.58 cw(c5193.15,3979.39) 5193.15,3961.28 ccw(c5193.15,3979.39) 5205.95,3966.58 ; 5205.95,3966.58 ccw(c5218.76,3953.78) 5200.65,3953.78 cw(c5218.76,3953.78) 5205.95,3966.58
  MidLayer2 w4: v1(4204.86,3444.71) 4243.67,3444.71 4255,3433.37 4454.86,3433.37 4456.86,3431.37 4513.19,3431.37 4531.86,3450.04 4556.86,3450.04 4568.19,3438.71 4639.56,3438.71 4667.23,3466.37 4786.86,3466.37 4870.52,3550.04 4881.86,3550.04 4915.19,3583.37 4973.52,3583.37 5048.19,3658.04 5167.33,3658.04 5169.29,3660 5169.29,3670 5169.29,3739.1 ; v1@4208.75,3440.82 cw(c4218.14,3431.43) 4218.14,3444.71 cw(c4218.14,3457.99) v1@4208.75,3448.6 ; v1@4211.57,3437.99 cw(c4227.79,3421.77) 4227.79,3444.71 cw(c4227.79,3467.64) v1@4211.57,3451.43 ; 5169.29,3680.84 5169.29,3739.1 ; v3@5185.76,3952.48 cw(c5167.93,3949.33) 5182.76,3938.95 ; v3@5194.45,3946.39 ccw(c5197.6,3928.56) 5182.76,3938.95 ; 5169.29,3739.1 5169.29,3797.36 5169.29,3816.78 5169.29,3890.9 5169.29,3914.15 cw(c5193.06,3914.15) 5175.68,3930.37 5182.76,3938.95
SPAREIO.2: J28.38 U8.W10 | length 2007.1
  Top Layer w4: J28.38@4323.39,3405.51 4323.52,3405.51 4323.52,3408.37 4340.19,3408.37 4381.86,3366.71 4381.86,3222.37 v1(4348.52,3189.04) ; J28.38@4345.51,3399.64 cw(c4345.51,3391.39) 4351.34,3397.22 ; J28.38@4347.39,3405.51 ccw(c4357.85,3405.51) J28.38@4350.45,3398.12 ; v1@4348.52,3194.54 ccw(c4348.52,3207.82) 4357.91,3198.43 ccw(c4367.3,3189.04) v1@4354.02,3189.04 ; v1@4348.52,3198.54 ccw(c4348.52,3221.48) 4364.74,3205.26 ccw(c4380.96,3189.04) v1@4358.02,3189.04 ; J28.38@4351.39,3405.51 ccw(c4371.5,3405.51) 4357.28,3391.29 ; v3(5232.52,3953.78) U8.W10@5252.2,3973.46 ; U8.W10@5244.7,3973.46 cw(c5226.6,3973.46) 5239.4,3960.66 cw(c5252.2,3947.86) U8.W10@5252.2,3965.96 ; U8.W10@5244.86,3973.46 cw(c5227.14,3973.46) 5239.67,3960.93 cw(c5252.2,3948.4) U8.W10@5252.2,3966.12 ; 5245.32,3966.58 ccw(c5258.13,3953.78) 5240.02,3953.78 cw(c5258.13,3953.78) 5245.32,3966.58 ; 5245.32,3966.58 cw(c5232.52,3979.39) 5232.52,3961.28 ccw(c5232.52,3979.39) 5245.32,3966.58
  MidLayer2 w4: v1(4348.52,3189.04) 4409.52,3250.04 4613.54,3250.04 4661.88,3298.37 4726.84,3298.37 4730.21,3295 4750.5,3274.71 4781.52,3274.71 4789.19,3282.37 4931.86,3425.04 4931.86,3441.71 4997.19,3507.04 4997.19,3584.37 5054.86,3642.04 5201.04,3642.04 5208.66,3649.66 5208.66,3660 5208.66,3670 5208.66,3685 ; v1@4348.52,3194.54 ccw(c4348.52,3207.82) 4357.91,3198.43 ccw(c4367.3,3189.04) v1@4354.02,3189.04 ; v1@4348.52,3198.54 ccw(c4348.52,3221.48) 4364.74,3205.26 ccw(c4380.96,3189.04) v1@4358.02,3189.04 ; 5208.66,3680.84 5208.66,3685 ; v3@5225.05,3953.13 cw(c5207.01,3951.55) 5220.88,3939.91 ; v3@5233.17,3946.31 ccw(c5234.75,3928.27) 5220.88,3939.91 ; 5208.66,3685 5208.66,3797.36 5208.66,3816.78 5208.66,3890.9 5208.66,3910.4 cw(c5250.39,3910.4) 5220.88,3939.91
SPAREIO.3: J28.39 U8.Y9 | length 1787.2
  Top Layer w4: v1@4210.35,3366.55 ccw(c4205.32,3375.04) 4215.19,3375.04 ; v1(4215.19,3358.37) 4215.19,3375.04 ; 4215.93,3375.78 ccw(c4208.81,3382.91) J28.39@4218.71,3384.75 ; 4217,3376.85 cw(c4224.49,3369.36) J28.39@4224.49,3379.95 ; v1@4220.03,3366.55 cw(c4225.06,3375.04) 4215.19,3375.04 ; J28.39@4246.61,3385.83 4248.52,3385.83 4248.52,3386.04 4247.68,3386.89 4242.86,3391.71 4231.86,3391.71 4215.19,3375.04 ; v3(5193.15,3914.41) U8.Y9@5212.83,3934.09 ; U8.Y9@5205.33,3934.09 cw(c5187.23,3934.09) 5200.03,3921.29 cw(c5212.83,3908.49) U8.Y9@5212.83,3926.59 ; U8.Y9@5205.49,3934.09 cw(c5187.77,3934.09) 5200.3,3921.56 cw(c5212.83,3909.03) U8.Y9@5212.83,3926.75 ; 5205.95,3927.21 cw(c5193.15,3940.02) 5193.15,3921.91 ccw(c5193.15,3940.02) 5205.95,3927.21 ; 5205.95,3927.21 ccw(c5218.76,3914.41) 5200.65,3914.41 cw(c5218.76,3914.41) 5205.95,3927.21
  MidLayer2 w4: v1(4215.19,3358.37) 4281.67,3358.37 4290,3366.71 4537.21,3366.71 4562.21,3391.71 4615.19,3391.71 4673.52,3450.04 4765.19,3450.04 4780.23,3435 4833.48,3435 4898.52,3500.04 ; v1@4219.08,3354.49 cw(c4228.47,3345.1) 4228.47,3358.37 cw(c4228.47,3371.65) v1@4219.08,3362.26 ; v1@4221.91,3351.66 cw(c4238.13,3335.44) 4238.13,3358.37 cw(c4238.13,3381.31) v1@4221.91,3365.09 ; 4844.24,3445.76 4898.52,3500.04 ; 5177.64,3876.97 5177.64,3890.9 ; 5181.76,3900.83 ccw(c5191.69,3890.9) 5177.64,3890.9 ; v3@5185.68,3913.76 cw(c5167.64,3912.18) 5181.51,3900.54 cw(c5195.38,3888.9) v3@5193.8,3906.94 ; 4898.52,3500.04 4898.52,3516.71 4904.19,3522.37 4940.19,3522.37 4948.52,3530.71 4948.52,3559.71 4963.86,3575.04 4976.52,3575.04 5051.52,3650.04 5170.64,3650.04 5177.64,3657.04 5177.64,3660 5177.64,3670 5177.64,3797.36 5177.64,3890.9
SPAREIO.4: J28.40 U8.Y10 | length 2998.9
  Top Layer w4: 4285.71,3366.71 cw(c4285.71,3350.59) J28.40@4297.11,3361.99 ; v1@4286.69,2933.37 ccw(c4263.76,2933.37) 4279.97,2949.59 ccw(c4296.19,2965.81) v1@4296.19,2942.87 ; 4288.45,3366.71 ccw(c4288.45,3378.96) J28.40@4297.11,3370.3 ; v1@4290.69,2933.37 ccw(c4277.41,2933.37) 4286.8,2942.76 ccw(c4296.19,2952.15) v1@4296.19,2938.87 ; v1(4296.19,2933.37) 4224.52,3005.04 4224.52,3341.71 4249.52,3366.71 4323.39,3366.71 4323.52,3366.71 4323.52,3366.14 J28.40@4323.39,3366.14 ; v3(5232.52,3914.41) U8.Y10@5252.2,3934.09 ; U8.Y10@5244.7,3934.09 cw(c5226.6,3934.09) 5239.4,3921.29 cw(c5252.2,3908.49) U8.Y10@5252.2,3926.59 ; U8.Y10@5244.86,3934.09 cw(c5227.14,3934.09) 5239.67,3921.56 cw(c5252.2,3909.03) U8.Y10@5252.2,3926.75 ; 5245.32,3927.21 cw(c5232.52,3940.02) 5232.52,3921.91 ccw(c5232.52,3940.02) 5245.32,3927.21 ; 5245.32,3927.21 ccw(c5258.13,3914.41) 5240.02,3914.41 cw(c5258.13,3914.41) 5245.32,3927.21
  MidLayer2 w4: v1(4296.19,2933.37) 4498.52,2933.37 4573.52,3008.37 4673.52,3008.37 4715.19,2966.71 4830.19,2966.71 5046.86,3183.37 5055.27,3183.37 5074.36,3202.46 5074.36,3224.02 5065,3233.37 5022.52,3233.37 4989.19,3266.71 4989.19,3340.04 5006.86,3357.71 5120.86,3357.71 5131.86,3368.71 5131.86,3470.04 5098.52,3503.37 5098.52,3557.35 5085.17,3570.71 5055,3570.71 5043.19,3558.9 5043.19,3542.04 5038.52,3537.37 5018.52,3537.37 5005.86,3550.04 5005.86,3581.71 5058.19,3634.04 5205.04,3634.04 5217.01,3646.01 5217.01,3660 5217.01,3670 5217.01,3797.36 5217.01,3890.9 ; v1@4300.08,2929.49 cw(c4309.47,2920.1) 4309.47,2933.37 cw(c4309.47,2946.65) v1@4300.08,2937.26 ; v1@4302.91,2926.66 cw(c4319.13,2910.44) 4319.13,2933.37 cw(c4319.13,2956.31) v1@4302.91,2940.09 ; 5217.01,3876.97 5217.01,3890.9 ; 5221.13,3900.83 ccw(c5231.06,3890.9) 5217.01,3890.9 ; v3@5225.05,3913.76 cw(c5207.01,3912.18) 5220.88,3900.54 cw(c5234.75,3888.9) v3@5233.17,3906.94
SPK.VOL: C105.2 U26.3 VR1.2 | length 7569
  Top Layer w4: U26.3@-389.13,5100 -184.81,5100 ; U26.3@-351.56,5095.89 cw(c-341.64,5085.97) -341.64,5100 cw(c-341.64,5114.03) U26.3@-351.56,5104.11 ; U26.3@-348.73,5093.06 cw(c-331.98,5076.31) -331.98,5100 cw(c-331.98,5123.69) U26.3@-348.73,5106.94 ; v1@-81.72,5438.28 cw(c-97.94,5422.06) -75,5422.06 cw(c-52.07,5422.06) v1@-68.28,5438.28 ; v1@-78.89,5441.11 cw(c-88.28,5431.72) -75,5431.72 cw(c-61.72,5431.72) v1@-71.11,5441.11 ; v1(-75,5445) -75,5400 -184.81,5290.19 -184.81,4929.81 -130,4875 -130,4820 -118.37,4808.37 290.19,4808.37 298.52,4800.04 298.52,4641.71 278.52,4621.71 278.52,4516.71 64.86,4303.04 64.86,4255.06 31.86,4222.06 31.86,3300.04 36.9,3295 135,3295 v4(175,3255) ; v4@65.19,2255 cw(c41.5,2255) 58.25,2238.25 cw(c75,2221.5) v4@75,2245.19 ; v4@69.19,2255 cw(c55.16,2255) 65.08,2245.08 cw(c75,2235.16) v4@75,2249.19 ; v4(75,2255) -40,2140 -40,1472.63 390.19,1042.44 390.19,604.81 ; v4@165.19,3255 ccw(c141.5,3255) 158.25,3271.75 ccw(c175,3288.5) v4@175,3264.81 ; v4@169.19,3255 ccw(c155.16,3255) 165.08,3264.92 ccw(c175,3274.84) v4@175,3260.81 ; VR1.2@403.3,562.06 ccw(c356.46,571.08) 390.19,604.81 ; VR1.2@407.23,561.31 ccw(c365.41,569.36) 395.52,599.48 ccw(c425.64,629.59) VR1.2@433.69,587.77 ; VR1.2@411.16,560.55 ccw(c374.35,567.64) 400.86,594.14 ccw(c427.36,620.65) VR1.2@434.45,583.84 ; VR1.2@415.09,559.8 ccw(c383.29,565.92) 406.19,588.81 ccw(c429.08,611.71) VR1.2@435.2,579.91 ; VR1.2@419.02,559.04 ccw(c392.23,564.19) 411.52,583.48 ccw(c430.81,602.77) VR1.2@435.96,575.98 ; VR1.2@432.94,591.7 cw(c423.92,638.54) 390.19,604.81 ; VR1.2@440,555 390.19,604.81
  MidLayer1 w4: v4@68.06,2261.94 ccw(c51.31,2278.69) 75,2278.69 ccw(c98.69,2278.69) v4@81.94,2261.94 ; v4@70.89,2259.11 ccw(c60.97,2269.03) 75,2269.03 ccw(c89.03,2269.03) v4@79.11,2259.11 ; v4(75,2255) 75,2625 -50,2750 -50,2905.94 -49.5,2906.44 -49.5,2907.12 -28.91,2927.71 17.29,2927.71 26.5,2918.5 26.5,2843.5 100,2770 205,2770 240,2805 240,2910 175,2975 v4(175,3255) ; v4@168.06,3248.06 cw(c151.31,3231.31) 175,3231.31 cw(c198.69,3231.31) v4@181.94,3248.06 ; v4@170.89,3250.89 cw(c160.97,3240.97) 175,3240.97 cw(c189.03,3240.97) v4@179.11,3250.89
  Bottom Layer w4: C105.2@-161.36,5444.25 -75.75,5444.25 v1(-75,5445) ; C105.2@-157.25,5440.14 cw(c-147.33,5430.22) -147.33,5444.25 cw(c-147.33,5458.28) C105.2@-157.25,5448.36 ; C105.2@-154.42,5437.31 cw(c-137.67,5420.56) -137.67,5444.25 cw(c-137.67,5467.93) C105.2@-154.42,5451.19 ; -99.75,5444.25 ccw(c-99.75,5469.75) v1@-81.72,5451.72 ; -96.12,5444.25 cw(c-96.12,5423.88) v1@-81.72,5438.28 ; -90.09,5444.25 ccw(c-90.09,5460.09) v1@-78.89,5448.89
SPK_L.SPK+: J34.1 U26.16 | length 1462.3
  Top Layer w12: J34.1@-171.19,6121.57 -171.03,6121.41 -30.16,6121.41 -18.75,6110 110,6110 140,6080 140,5855 60,5775 60,5260 27.02,5227.02 27.02,5207.02 ; J34.1@-154.55,6104.93 cw(c-114.77,6065.15) -114.77,6121.41 ; J34.1@-154.55,6138.2 ccw(c-114.01,6178.75) -114.01,6121.41 ; U26.16@-30.87,5200 20,5200 27.02,5207.02 ; U26.16@-0.8,5194.83 ccw(c6.81,5206.4) 16.61,5196.61 ; U26.16@5.79,5204.85 ccw(c15.08,5218.97) 27.02,5207.02 ; U26.16@6.71,5195.89 cw(c16.63,5185.97) 16.63,5200 cw(c16.63,5214.03) U26.16@6.71,5204.11
SPK_L.SPK-: C106.1 J34.2 U26.14 | length 2236.5
  Top Layer w12: U26.14@-30.87,5100 50,5100 130.87,5019.13 130.87,4980.87 85,4935 v1(85,4905) v1@85,4900 ; U26.14@6.71,5095.89 cw(c16.63,5085.97) 16.63,5100 cw(c16.63,5114.03) U26.14@6.71,5104.11 ; v1@81.11,4908.89 ccw(c71.72,4918.28) 85,4918.28 ccw(c98.28,4918.28) v1@88.89,4908.89
  MidLayer1 w12: J34.2@-103,6160.94 -5.94,6160.94 65,6090 65,5965 53.19,5953.19 53.19,5302.03 -13.48,5235.36 -13.48,5028.48 67.28,4947.72 67.28,4922.72 v1(85,4905) ; J34.2@-86.36,6144.3 cw(c-46.2,6104.14) -46.2,6160.94 cw(c-46.2,6217.74) J34.2@-86.36,6177.57 ; v1@79.5,4905 ccw(c66.22,4905) 75.61,4914.39 ccw(c85,4923.78) v1@85,4910.5
  Bottom Layer w12: C106.1@6.06,4845.28 50.28,4845.28 85,4880 v1(85,4905) ; C106.1@20.83,4858.7 ccw(c42.13,4885.1) 66.11,4861.11 ; C106.1@28.36,4868.04 ccw(c50.56,4895.56) 75.56,4870.56 ; C106.1@35.89,4877.38 ccw(c58.99,4906.01) 85,4880 ; v1@81.11,4901.11 cw(c71.72,4891.72) 85,4891.72 cw(c98.28,4891.72) v1@88.89,4901.11
SPK_R.SPK+: J35.1 U26.9 | length 9285
  Top Layer w12: U26.9@-68.44,4854.11 ccw(c-77.67,4863.34) v1@-64.62,4863.34 ; v1@-64.62,4864.72 ccw(c-49.61,4864.72) U26.9@-60.22,4854.11
  Top Layer w23: v1(-64.62,4868.69) -64.62,4850.38 U26.9@-64.24,4850
  MidLayer2 w12: v1(-64.62,4868.69) 8.69,4868.69 69.97,4929.97 96.62,4929.97 223.89,5057.24 ; v1@-60.73,4864.8 cw(c-51.34,4855.41) -51.34,4868.69 cw(c-51.34,4881.97) v1@-60.73,4872.58 ; 223.89,5057.29 250,5083.41 250,5182.63 236,5196.63 236,5563.37 284.63,5612 1465.63,5612 1606.93,5753.3 1840.93,5753.3 1897.63,5810 2693,5810 2735,5852 2821,5852 2861,5812 4473,5812 4507.5,5777.5 4795.53,5777.5 4806.49,5766.54 5231.63,5766.54 5274.09,5809 5821.22,5809 6090,6077.78 6090,6232.63 6198.37,6341 6328,6341 6374.99,6387.99 6705.03,6387.99 6761.85,6444.81 6970.32,6444.81 6972.94,6442.19 7137.81,6442.19 7179.52,6400.48 7271.5,6308.5 7725.87,6308.5 7784.36,6250.01 J35.1@7784.36,6160.94 ; J35.1@7767.73,6177.57 ccw(c7727.56,6217.74) 7784.36,6217.74 ccw(c7841.16,6217.74) J35.1@7801,6177.57
SPK_R.SPK-: C107.1 J35.2 U26.11 | length 10485.4
  Top Layer w12: U26.11@-30.87,4950 50,4950 60,4940 60,4895 75,4880 ; U26.11@6.71,4945.89 cw(c16.63,4935.97) 16.63,4950 cw(c16.63,4964.03) U26.11@6.71,4954.11 ; v1@108.54,4895.78 cw(c75,4923.53) 75,4880 ; v1(112.78,4892.28) 100.5,4880 ; v1@117.79,4888.14 cw(c100.5,4902.44) 100.5,4880 ; 75,4880 100.5,4880
  MidLayer2 w12: v1@107.28,4892.28 cw(c94,4892.28) 103.39,4882.89 cw(c112.78,4873.5) v1@112.78,4886.78 ; v1@108.89,4896.17 ccw(c99.5,4905.56) 112.78,4905.56 ccw(c126.06,4905.56) v1@116.67,4896.17 ; v1@414.5,4930 ccw(c401.22,4930) 410.61,4939.39 ccw(c420,4948.78) v1@420,4935.5 ; v1(420,4930) 369.88,4980.12 169.4,4980.12 112.78,4923.5 v1(112.78,4892.28) 67.69,4847.19 -77.19,4847.19 -90,4860 -90,4880 -79.81,4890.19 7.56,4890.19 63.34,4945.97 89.94,4945.97 234,5090.03 234,5176 220,5190 220,5570 278,5628 1459,5628 1600.3,5769.3 1834.3,5769.3 1891,5826 2673.37,5826 2686.37,5826 2728.37,5868 2827.63,5868 2867.13,5828.5 4479.13,5828.5 4514.13,5793.5 4802.16,5793.5 4813.12,5782.54 5225,5782.54 5267.46,5825 5814.59,5825 6074,6084.41 6074,6239.25 6191.75,6357 6320.01,6357 6367,6403.99 ; 6366.34,6403.99 6367,6403.99 ; J35.2@7835.92,6138.2 ccw(c7795.75,6178.37) 7852.55,6178.37 ccw(c7909.36,6178.37) J35.2@7869.19,6138.2 ; J35.2@7852.55,6121.57 7852.55,6204.45 7732,6325 7277.63,6325 7144.44,6458.19 6979.57,6458.19 6976.95,6460.81 6755.22,6460.81 6698.4,6403.99 6367,6403.99
  Bottom Layer w4: v1(420,4930) v1@422.37,4930
  Bottom Layer w12: v1@420,4924.5 cw(c420,4911.22) 429.39,4920.61 cw(c438.78,4930) v1@425.5,4930 ; v1(420,4930) 446.06,4903.94 ; C107.1@432.11,4884.09 ccw(c424.97,4903.93) 446.06,4903.93 ; C107.1@446.06,4845.28 446.06,4903.94 ; C107.1@460.02,4884.09 cw(c467.16,4903.93) 446.06,4903.93
SW#.D0: J28.1 R102.2 SW1.2 U8.K1 | length 8616.6
  Top Layer w4: v1@4173.36,4440.71 ccw(c4150.42,4440.71) 4166.64,4456.93 ccw(c4182.86,4473.14) v1@4182.86,4450.21 ; v1@4177.36,4440.71 ccw(c4164.08,4440.71) 4173.47,4450.1 ccw(c4182.86,4459.49) v1@4182.86,4446.21 ; 4215.19,4141.52 ccw(c4232.15,4141.52) J28.1@4220.16,4129.53 ; 4215.19,4151.17 ccw(c4241.8,4151.17) J28.1@4222.98,4132.35 ; 4215.19,4160.83 ccw(c4251.46,4160.83) J28.1@4225.81,4135.18 ; 4215.19,4170.49 ccw(c4261.12,4170.49) J28.1@4228.64,4138.01 ; J28.1@4219.18,4131.34 ccw(c4215.19,4129.44) 4215.19,4133.86 ; J28.1@4219.18,4136.38 cw(c4215.19,4138.28) 4215.19,4133.86 ; J28.1@4246.61,4133.86 4215.19,4133.86 ; v1@4293.28,1571.72 ccw(c4277.06,1587.93) 4300,1587.93 ccw(c4322.93,1587.93) v1@4306.72,1571.72 ; v1@4296.11,1568.89 ccw(c4286.72,1578.28) 4300,1578.28 ccw(c4313.28,1578.28) v1@4303.89,1568.89 ; v1(4300,1565) 4300,1595 4312,1607 4312,1902.65 4321.46,1912.1 4321.46,1933.23 4290.52,1964.16 4290.52,2304.48 4256.86,2338.14 4256.86,2481.67 3848.52,2890 3848.52,3288.67 3597.19,3540 3597.19,3789.77 3832.19,4024.77 3832.19,4050 3931.86,4149.67 3931.86,4316.71 3925.82,4322.75 3925.82,4869 3981.86,4925.04 4148.52,4925.04 4165.19,4908.37 4165.19,4835 4150,4819.81 4150,4473.56 v1(4182.86,4440.71) 4198.52,4425.04 4198.52,4383.37 4156.86,4341.71 4156.86,4283.37 4215.19,4225.04 4215.19,4133.86 ; v1@4344.68,4416.55 ccw(c4339.66,4425.04) 4349.52,4425.04 ; v1(4349.52,4408.37) 4349.52,4425.04 ; v1@4354.36,4416.55 cw(c4359.39,4425.04) 4349.52,4425.04 ; U8.K1@4892.57,4322.49 ccw(c4879.77,4309.69) 4879.77,4327.8 ccw(c4879.77,4345.9) U8.K1@4892.57,4333.1 ; U8.K1@4897.87,4327.8 4870,4327.8 4860,4327.8 4841,4327.8 4812.2,4327.8 4754.96,4385.04 4572,4385.04 4545,4358.04 4512.54,4358.04 4428.88,4441.71 4366.19,4441.71 4349.52,4425.04 ; R102.2@5302.92,957.23 ccw(c5287.01,941.32) 5287.01,963.82 ccw(c5287.01,986.32) R102.2@5302.92,970.41 ; R102.2@5303.41,957.23 cw(c5287.5,941.32) 5310,941.32 cw(c5332.5,941.32) R102.2@5316.59,957.23 ; R102.2@5305.75,960.06 ccw(c5296.67,950.98) 5296.67,963.82 ccw(c5296.67,976.66) R102.2@5305.75,967.58 ; R102.2@5306.24,960.06 cw(c5297.16,950.98) 5310,950.98 cw(c5322.84,950.98) R102.2@5313.76,960.06 ; SW1.2@5307.02,911.31 ccw(c5299.84,918.49) SW1.2@5310,918.49 ; 5310,921.96 ccw(c5341.83,921.96) SW1.2@5321.83,897.2 ; 5310,930.33 ccw(c5348.58,930.33) SW1.2@5324.35,900.31 ; 5310,938.7 ccw(c5355.34,938.7) SW1.2@5326.86,903.42 ; 5310,947.07 ccw(c5362.1,947.07) SW1.2@5329.37,906.54 ; R102.2@5310,955.44 ccw(c5368.86,955.44) SW1.2@5331.88,909.65 ; SW1.2@5327.52,896.81 5310,914.33 R102.2@5310,963.82 ; SW1.2@5334.4,912.76 cw(c5375.62,963.81) R102.2@5310,963.82 ; v1@5364.02,1010.04 ccw(c5341.09,1010.04) 5357.31,1026.26 ccw(c5373.52,1042.48) v1@5373.52,1019.54 ; v1@5368.02,1010.04 ccw(c5354.75,1010.04) 5364.14,1019.43 ccw(c5373.52,1028.82) v1@5373.52,1015.54 ; v1(5373.52,1010.04) 5348.56,1035 5290,1035 5270,1015 5270,975 5281.18,963.82 R102.2@5310,963.82 ; 4880.15,4327.8 cw(c4880.15,4310.07) 4892.68,4322.6 ccw(c4880.15,4310.07) 4880.15,4327.8 ; 4880.15,4327.8 ccw(c4880.15,4345.52) 4892.68,4332.99 cw(c4880.15,4345.52) 4880.15,4327.8
  MidLayer1 w4: v4@4283.06,1281.94 ccw(c4266.31,1298.69) 4290,1298.69 ccw(c4313.69,1298.69) v4@4296.94,1281.94 ; 4283.6,1548.35 ccw(c4266.95,1565) v1@4290.5,1565 ; 4284.22,1548.96 cw(c4300,1533.18) v1@4300,1555.5 ; v4@4285.89,1279.11 ccw(c4275.97,1289.03) 4290,1289.03 ccw(c4304.03,1289.03) v4@4294.11,1279.11 ; v4(4290,1275) 4290,1320 4281.86,1328.14 4281.86,1546.6 4300,1564.75 v1(4300,1565) ; 4290.43,1555.18 ccw(c4280.61,1565) v1@4294.5,1565 ; 4291.05,1555.79 cw(c4300,1546.84) v1@4300,1559.5
  MidLayer2 w4: v1(4182.86,4440.71) 4266.19,4440.71 4298.52,4408.37 v1(4349.52,4408.37) ; v1@4186.75,4436.82 cw(c4196.14,4427.43) 4196.14,4440.71 cw(c4196.14,4453.99) v1@4186.75,4444.6 ; v1@4189.57,4433.99 cw(c4205.79,4417.77) 4205.79,4440.71 cw(c4205.79,4463.64) v1@4189.57,4447.43 ; v4@4290.03,1269.19 cw(c4290.1,1255.41) 4299.85,1265.15 cw(c4309.59,1274.9) v4@4295.81,1274.97 ; v4(4290,1275) 4306.63,1258.37 ; v4@4290.05,1265.19 cw(c4290.17,1241.93) 4306.62,1258.38 ; v4@4299.81,1274.95 ccw(c4323.07,1274.83) 4306.62,1258.38 ; v1@4342.81,4401.66 ccw(c4326.59,4385.44) 4326.59,4408.37 ccw(c4326.59,4431.31) v1@4342.81,4415.09 ; v1@4345.64,4404.49 ccw(c4336.25,4395.1) 4336.25,4408.37 ccw(c4336.25,4421.65) v1@4345.64,4412.26 ; v1@5366.81,1016.76 ccw(c5350.59,1032.98) 5373.52,1032.98 ccw(c5396.46,1032.98) v1@5380.24,1016.76 ; v1@5369.64,1013.93 ccw(c5360.25,1023.32) 5373.52,1023.32 ccw(c5386.8,1023.32) v1@5377.41,1013.93 ; v1(5373.52,1010.04) 5373.52,1033.37 5290.19,1116.71 5023.52,1116.71 4881.86,1258.37 4306.63,1258.37
SW#.D1: J28.2 R103.2 SW2.2 U8.U3 | length 7945.9
  Top Layer w4: v1@3630.69,3991.71 cw(c3607.76,3991.71) 3623.97,3975.49 cw(c3640.19,3959.27) v1@3640.19,3982.21 ; v1@3634.69,3991.71 cw(c3621.41,3991.71) 3630.8,3982.32 cw(c3640.19,3972.93) v1@3640.19,3986.21 ; v1(3640.19,3991.71) 3606.86,3958.37 3540.19,3958.37 3523.52,3941.71 3523.52,2347.02 3503,2326.5 3503,1848 3480,1825 3421.31,1825 3408,1811.69 3408,1373.31 3423.27,1358.04 3658.04,1358.04 3670,1370 3696.86,1370 3706.86,1360 v1(3706.86,1308.37) ; v1@3700.14,1315.09 ccw(c3683.92,1331.31) 3706.86,1331.31 ccw(c3729.79,1331.31) v1@3713.57,1315.09 ; v1@3702.97,1312.26 ccw(c3693.58,1321.65) 3706.86,1321.65 ccw(c3720.14,1321.65) v1@3710.75,1312.26 ; v1(4115.19,4091.71) 4140.19,4116.71 J28.2@4316.86,4116.71 ; v1@4115.19,4097.21 ccw(c4115.19,4110.49) 4124.58,4101.1 ccw(c4133.97,4091.71) v1@4120.69,4091.71 ; v1@4115.19,4101.21 ccw(c4115.19,4124.14) 4131.41,4107.93 ccw(c4147.63,4091.71) v1@4124.69,4091.71 ; 4280.96,4116.71 cw(c4280.96,4093.87) J28.2@4297.11,4110.02 ; 4290.62,4116.71 cw(c4290.62,4103.53) J28.2@4299.93,4112.85 ; 4293.2,4116.71 ccw(c4293.2,4122.24) J28.2@4297.11,4118.33 ; J28.2@4323.52,4114.17 J28.2@4323.39,4114.17 4459.39,4114.17 4481.86,4091.71 4481.86,4026.04 4491.19,4016.71 4506.86,4016.71 4537.39,4047.24 4556.69,4066.54 ; J28.2@4349.67,4110.02 cw(c4359.69,4099.99) 4359.69,4114.17 cw(c4359.69,4128.35) J28.2@4349.67,4118.33 ; 4556.86,4066.71 4556.69,4066.54 ; 4855.26,4028.34 4860,4028.34 4870,4028.34 4936.73,4028.34 ; 4856.86,4028.34 4776.37,4028.34 4773.24,4025.21 4724.79,4025.21 4683.46,4066.54 4674.63,4075.37 4565.52,4075.37 4556.69,4066.54 ; v1@5728.28,1063.82 cw(c5712.06,1047.61) 5735,1047.61 cw(c5757.93,1047.61) v1@5741.72,1063.82 ; v1@5731.11,1066.65 cw(c5721.72,1057.26) 5735,1057.26 cw(c5748.28,1057.26) v1@5738.89,1066.65 ; v1(5735,1070.54) 5735,1013.82 R103.2@5785,963.82 5785,936.73 5805.02,916.71 SW2.2@5805.02,896.81 ; 5768.25,980.57 cw(c5751.5,963.82) R103.2@5775.19,963.82 ; 5769.44,979.38 ccw(c5784.51,994.45) R103.2@5784.51,973.14 ; R103.2@5775.08,973.74 cw(c5765.16,963.82) R103.2@5779.19,963.82 ; R103.2@5776.27,972.55 ccw(c5784.51,980.79) R103.2@5784.51,969.14 ; R103.2@5778.41,957.23 cw(c5762.5,941.32) 5785,941.32 cw(c5807.5,941.32) R103.2@5791.59,957.23 ; R103.2@5781.24,960.06 cw(c5772.16,950.98) 5785,950.98 cw(c5797.84,950.98) R103.2@5788.76,960.06 ; 5784.39,937.33 cw(c5760.87,913.81) SW2.2@5791.26,900.27 ; 5788.51,933.22 cw(c5766.56,911.28) SW2.2@5794.91,898.64 ; 5792.62,929.11 cw(c5772.25,908.74) SW2.2@5798.56,897.01 ; 5796.74,924.99 cw(c5777.95,906.2) SW2.2@5802.22,895.39 ; 5800.85,920.88 cw(c5783.64,903.67) SW2.2@5805.87,893.76 ; 4936.73,4028.34 ccw(c4936.73,4067.02) 4964.08,4039.67 ; 4936.73,4028.34 ccw(c4936.73,4067.02) 4964.08,4039.67 ; 4964.08,4039.67 cw(c4976.61,4027.14) 4976.61,4044.86 ccw(c4976.61,4027.14) 4964.08,4039.67 ; 4964.08,4039.67 ccw(c4951.55,4052.2) 4969.27,4052.2 cw(c4951.55,4052.2) 4964.08,4039.67
  Bottom Layer w4: v1(3640.19,3991.71) 3748.52,4100.04 4080,4100.04 4088.33,4091.71 v1(4115.19,4091.71) ; v1@3640.19,3997.21 ccw(c3640.19,4010.49) 3649.58,4001.1 ccw(c3658.97,3991.71) v1@3645.69,3991.71 ; v1@3640.19,4001.21 ccw(c3640.19,4024.14) 3656.41,4007.93 ccw(c3672.63,3991.71) v1@3649.69,3991.71 ; v1(3706.86,1308.37) 3757.52,1359.04 4758.56,1359.04 4853.6,1264 5006.63,1264 5018,1275.37 5075.63,1275.37 5125,1226 5169.71,1226 5179,1216.71 5206.65,1216.71 5249.31,1259.37 5465.95,1259.37 5640.33,1085 5716.31,1085 5728,1073.31 5728,1071.28 5735,1064.28 v1(5735,1070.54) ; v1@3706.86,1313.87 ccw(c3706.86,1327.15) 3716.25,1317.76 ccw(c3725.64,1308.37) v1@3712.36,1308.37 ; v1@3706.86,1317.87 ccw(c3706.86,1340.81) 3723.07,1324.59 ccw(c3739.29,1308.37) v1@3716.36,1308.37 ; v1@4108.47,4084.99 ccw(c4092.26,4068.77) 4092.26,4091.71 ccw(c4092.26,4114.64) v1@4108.47,4098.43 ; v1@4111.3,4087.82 ccw(c4101.91,4078.43) 4101.91,4091.71 ccw(c4101.91,4104.99) v1@4111.3,4095.6 ; 5718.43,1082.89 ccw(c5727.96,1092.42) v1@5732.09,1079.58 ; 5721.77,1079.54 cw(c5712.77,1070.54) v1@5725.5,1070.54 ; 5723.06,1078.25 ccw(c5730.22,1085.41) v1@5733.32,1075.78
